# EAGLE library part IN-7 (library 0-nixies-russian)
IN-7: large symbol topview nixie tube
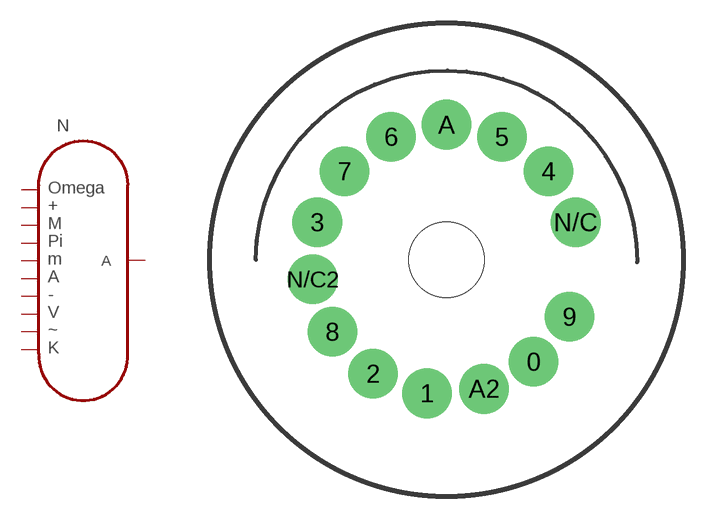
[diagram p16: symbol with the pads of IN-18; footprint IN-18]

Designator prefix N

## IN-7  [IN-18]
0  P$10
1  P$1
3  P$8
4  A
6  P$5
7  P$6
8  P$3
9  P$7
A  P$2
A2  P$9
N/C  P$4

## Footprint IN-18 (pad centres in mm)
May be used with socket: PL31-P
drill 2.3 pad 3.2 round: 0 5.8,-6.8; 1 -1.3,-8.9; 2 -4.9,-7.6; 3 -8.6,2.5; 4 6.8,5.9; 5 3.7,8.2; 6 -3.7,8.2; 7 -6.8,5.9; 8 -7.6,-4.8; 9 8.2,-3.8; A 0,9; A2 2.5,-8.6; N/C 8.6,2.5; N/C2 -8.9,-1.3
hole 5 at 0,0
